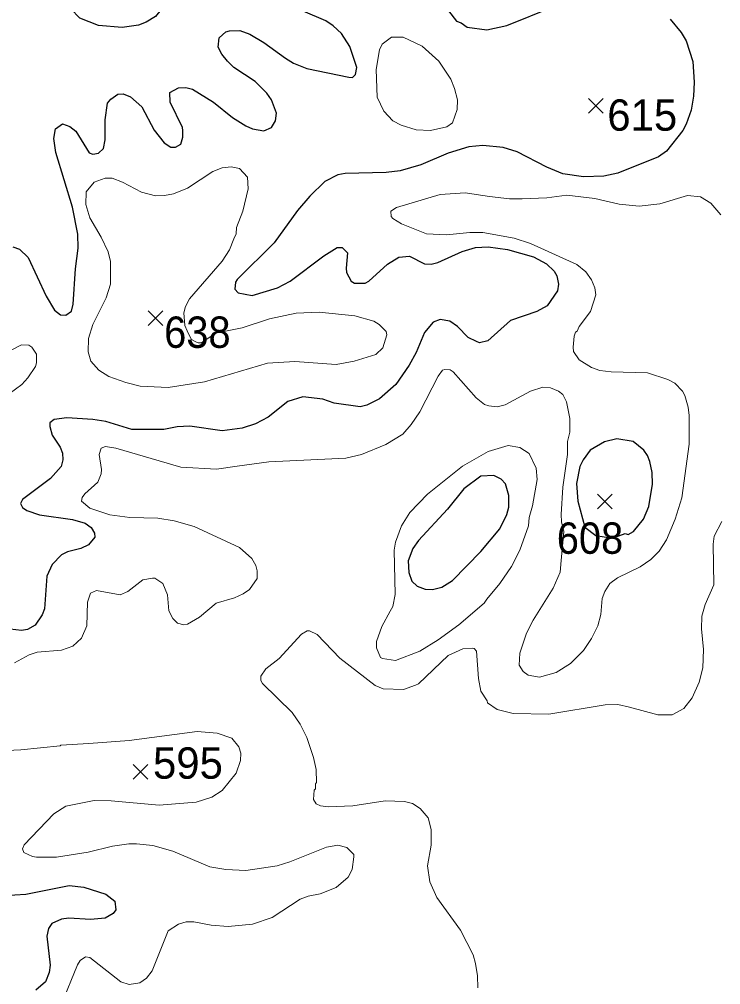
# Model space of a CAD drawing. Extents: x 423 to 448.8, y 7456.3 to 7484.
# Drawn here: x 434.858 to 436.648, y 7460.704 to 7463.168 of the extents above; entities that cross this region are included whole.
import ezdxf
from ezdxf.enums import TextEntityAlignment as Align

# ---------------------------------------------------------------- set-up
doc = ezdxf.new("R2010")
doc.units = 0
doc.header["$LTSCALE"] = 0.032
for name, color, linetype, lineweight in [('1', 7, 'Continuous', 25), ('2', 7, 'Continuous', 13), ('21', 7, 'Continuous', 25)]:
    doc.layers.add(name, color=color, linetype=linetype, lineweight=lineweight)
doc.layers.add('61', color=7, linetype='Continuous')

msp = doc.modelspace()

# ---------------------------------------------------------------- linework, layer by layer
at = {"layer": '1'}
for points in [[(434.9786, 7463.2394), (434.9778, 7463.2502), (434.9925, 7463.3028), (435.008, 7463.3236), (435.0475, 7463.3538), (435.0792, 7463.3616), (435.1062, 7463.3623), (435.148, 7463.3538), (435.1697, 7463.3415), (435.2083, 7463.3066), (435.2223, 7463.2811), (435.2315, 7463.2533), (435.2307, 7463.2146), (435.2199, 7463.193), (435.2052, 7463.1752), (435.182, 7463.1605), (435.1619, 7463.1527), (435.1202, 7463.1473), (435.0598, 7463.152), (435.0126, 7463.1705), (434.9894, 7463.1945)], [(436.4505, 7461.8919), (436.4644, 7461.9245), (436.4737, 7461.9817), (436.4729, 7462.0111), (436.4668, 7462.039), (436.4613, 7462.0544), (436.452, 7462.0683), (436.4242, 7462.09), (436.3825, 7462.097), (436.3515, 7462.0892), (436.3151, 7462.0683), (436.2966, 7462.0436), (436.2881, 7462.0266), (436.2803, 7461.9833), (436.2834, 7461.9384), (436.3009, 7461.872), (436.329, 7461.8501), (436.3715, 7461.8439), (436.4043, 7461.8556), (436.4118, 7461.8533), (436.4258, 7461.861)], [(436.0355, 7461.8092), (436.0839, 7461.8672), (436.1025, 7461.9044), (436.1071, 7461.9229), (436.1071, 7461.9523), (436.0986, 7461.9825), (436.0878, 7461.9941), (436.0692, 7462.0034), (436.0359, 7462.0018), (435.9926, 7461.9693), (435.9509, 7461.9175), (435.8766, 7461.8379), (435.8619, 7461.8169), (435.8503, 7461.786), (435.8518, 7461.7559), (435.8596, 7461.7342), (435.8735, 7461.721), (435.8936, 7461.7133), (435.9122, 7461.7125), (435.9361, 7461.7187), (435.9632, 7461.7357)]]:
    msp.add_lwpolyline(points, close=True, dxfattribs=at)
for points in [[(435.9532, 7463.1898), (435.9741, 7463.1628), (435.9856, 7463.1589), (436.0011, 7463.1481), (436.0514, 7463.1411), (436.1025, 7463.152), (436.22, 7463.1999)], [(434.9631, 7462.4133), (434.9763, 7462.4125), (434.991, 7462.4233), (434.9956, 7462.4412), (435.001, 7462.5309), (435.008, 7462.5835), (435.0072, 7462.6191), (434.9941, 7462.6887), (434.9508, 7462.8279), (434.9461, 7462.8635), (434.95, 7462.8882), (434.9686, 7462.9013), (434.9871, 7462.8944), (435.0026, 7462.882), (435.0366, 7462.8271), (435.0459, 7462.8232), (435.0598, 7462.8263), (435.073, 7462.8379), (435.0768, 7462.8604), (435.0768, 7462.9114), (435.083, 7462.9539), (435.0915, 7462.964), (435.1093, 7462.9764), (435.1233, 7462.9779), (435.1418, 7462.9702), (435.1704, 7462.9446), (435.2021, 7462.8851), (435.2277, 7462.8526), (435.2447, 7462.8418), (435.2563, 7462.8418), (435.2702, 7462.8488), (435.2756, 7462.8666), (435.2749, 7462.8836), (435.2741, 7462.8913), (435.2431, 7462.9563), (435.2423, 7462.981), (435.264, 7462.9926), (435.2826, 7462.9934), (435.2996, 7462.9895), (435.3538, 7462.9563), (435.4024, 7462.9176), (435.4357, 7462.8959), (435.4528, 7462.8882), (435.4821, 7462.8835), (435.5015, 7462.8921), (435.5115, 7462.9083), (435.5146, 7462.9284), (435.5015, 7462.9625), (435.4899, 7462.9795), (435.4597, 7463.0089), (435.4056, 7463.0452), (435.3893, 7463.0607), (435.3746, 7463.0785), (435.3653, 7463.0971), (435.3677, 7463.1203), (435.3854, 7463.1357), (435.394, 7463.138), (435.421, 7463.1396), (435.4466, 7463.1295), (435.4822, 7463.1086), (435.537, 7463.0684), (435.558, 7463.056), (435.592, 7463.0421), (435.6987, 7463.0205), (435.708, 7463.0197), (435.7157, 7463.0266), (435.7196, 7463.0445), (435.7018, 7463.0986), (435.6801, 7463.1318), (435.6592, 7463.1512), (435.6399, 7463.1636), (435.5827, 7463.1883)], [(436.5193, 7463.1682), (436.5472, 7463.1341), (436.5596, 7463.1125), (436.5766, 7463.0599), (436.5805, 7463.0073), (436.5789, 7462.9718), (436.5727, 7462.9362), (436.5596, 7462.9006), (436.5511, 7462.8836), (436.51, 7462.8317), (436.4891, 7462.817), (436.3856, 7462.7753), (436.35, 7462.7675), (436.2974, 7462.766), (436.2448, 7462.7737), (436.2046, 7462.7907), (436.1288, 7462.8294), (436.0932, 7462.841), (436.0406, 7462.8456), (436.005, 7462.8426), (435.9524, 7462.8263), (435.8828, 7462.7962), (435.8302, 7462.7807), (435.7946, 7462.7768), (435.6894, 7462.7745), (435.6709, 7462.7706), (435.6376, 7462.7536), (435.5997, 7462.7165), (435.568, 7462.6801), (435.5084, 7462.5974), (435.4141, 7462.5038), (435.4094, 7462.4968), (435.4079, 7462.479), (435.4164, 7462.4697), (435.452, 7462.4628), (435.5169, 7462.4829), (435.5494, 7462.4991), (435.6353, 7462.5641), (435.6693, 7462.5858), (435.6817, 7462.585), (435.6956, 7462.5718), (435.6917, 7462.5324), (435.6933, 7462.5216), (435.7049, 7462.4999), (435.7134, 7462.4945), (435.7404, 7462.4945), (435.7498, 7462.4991), (435.7977, 7462.5432), (435.8263, 7462.561), (435.8534, 7462.5634), (435.8921, 7462.544), (435.9091, 7462.5425), (435.9261, 7462.5471), (435.988, 7462.575), (436.022, 7462.585), (436.0545, 7462.5873), (436.104, 7462.5803), (436.1705, 7462.5618), (436.203, 7462.544)], [(434.8417, 7462.5873), (434.8587, 7462.5811), (434.8804, 7462.5602), (434.9268, 7462.4613), (434.9477, 7462.4257), (434.9631, 7462.4133)], [(436.203, 7462.544), (436.2231, 7462.5254), (436.2301, 7462.5131), (436.2339, 7462.4922), (436.2316, 7462.4752), (436.2053, 7462.4365), (436.1783, 7462.4218), (436.1117, 7462.3994), (436.0537, 7462.3468), (436.0321, 7462.3421), (436.0251, 7462.3452), (436.0035, 7462.356), (435.9764, 7462.3839), (435.9563, 7462.3978), (435.9323, 7462.4017), (435.9145, 7462.3947), (435.8921, 7462.3685), (435.8704, 7462.3174), (435.8526, 7462.2849), (435.8186, 7462.2362), (435.7776, 7462.199), (435.7451, 7462.1828), (435.7281, 7462.1789), (435.6616, 7462.1882), (435.6322, 7462.1983), (435.5812, 7462.2045), (435.5432, 7462.1928), (435.4929, 7462.1526), (435.4605, 7462.1356), (435.4265, 7462.124), (435.3754, 7462.1178), (435.2934, 7462.1294), (435.2609, 7462.1279), (435.2269, 7462.1209), (435.1449, 7462.1209), (435.0784, 7462.141), (435.0459, 7462.1465), (434.9794, 7462.1511), (434.9469, 7462.1464), (434.936, 7462.138), (434.936, 7462.1287), (434.9422, 7462.1062), (434.9624, 7462.0761), (434.9686, 7462.0606), (434.9693, 7462.0436), (434.9647, 7462.0266), (434.9376, 7461.9956), (434.8657, 7461.9423), (434.861, 7461.9322), (434.8657, 7461.9221), (434.8773, 7461.9144), (434.9098, 7461.9028), (434.9933, 7461.8912), (435.0258, 7461.8819), (435.0412, 7461.8711), (435.0498, 7461.8564), (435.0505, 7461.8463), (435.0343, 7461.8262), (435.015, 7461.8169), (434.9809, 7461.8085), (434.9655, 7461.8007), (434.9415, 7461.7767), (434.9283, 7461.7466), (434.9221, 7461.6631), (434.9167, 7461.6476), (434.8982, 7461.6213), (434.8789, 7461.6104), (434.8634, 7461.6081), (434.82, 7461.6128)], [(434.8185, 7460.9314), (434.8742, 7460.9352), (434.9856, 7460.9568), (435.0227, 7460.953), (435.0784, 7460.9352), (435.1016, 7460.9174), (435.1047, 7460.895), (435.0977, 7460.8857), (435.0769, 7460.8741), (435.0397, 7460.8702), (434.984, 7460.8741), (434.9655, 7460.871), (434.9407, 7460.8602), (434.9322, 7460.8478), (434.9283, 7460.8277), (434.9368, 7460.7535), (434.9338, 7460.7349), (434.9245, 7460.7109), (434.9005, 7460.69)]]:
    msp.add_lwpolyline(points, dxfattribs=at)
at = {"layer": '2'}
for points in [[(435.9686, 7462.9911), (435.9593, 7463.0151), (435.9284, 7463.0607), (435.8859, 7463.0993), (435.8379, 7463.1218), (435.8271, 7463.1225), (435.8078, 7463.1218), (435.7838, 7463.104), (435.7776, 7463.0901), (435.7683, 7463.0398), (435.7714, 7462.9687), (435.7884, 7462.9331), (435.8116, 7462.9091), (435.8325, 7462.8975), (435.8704, 7462.8859), (435.9076, 7462.8843), (435.9493, 7462.8936), (435.9632, 7462.9037), (435.9756, 7462.9377), (435.9764, 7462.9625)], [(435.4055, 7462.6074), (435.411, 7462.6206), (435.4125, 7462.6368), (435.428, 7462.6778), (435.4419, 7462.7351), (435.4404, 7462.7652), (435.4195, 7462.7869), (435.3986, 7462.7915), (435.3754, 7462.7884), (435.3522, 7462.7791), (435.2872, 7462.7366), (435.2517, 7462.7227), (435.2285, 7462.718), (435.2053, 7462.7172), (435.1697, 7462.7265), (435.1217, 7462.7521), (435.0946, 7462.7621), (435.0768, 7462.7621), (435.049, 7462.752), (435.0289, 7462.7273), (435.0274, 7462.6949), (435.0381, 7462.6608), (435.0668, 7462.6121), (435.0846, 7462.5742), (435.0908, 7462.5494), (435.0908, 7462.4922), (435.0799, 7462.4566), (435.0459, 7462.3886), (435.0343, 7462.353), (435.0335, 7462.319), (435.0405, 7462.2957), (435.0613, 7462.2725), (435.0861, 7462.2563), (435.1295, 7462.2408), (435.1666, 7462.2315), (435.2377, 7462.2284), (435.3306, 7462.2423), (435.4914, 7462.2903), (435.561, 7462.2942), (435.6662, 7462.2872), (435.7126, 7462.2957), (435.7675, 7462.312), (435.7861, 7462.329), (435.7961, 7462.3623), (435.7938, 7462.3707), (435.776, 7462.3893), (435.7629, 7462.3978), (435.7142, 7462.411), (435.6229, 7462.4202), (435.5641, 7462.4179), (435.4961, 7462.4032), (435.4265, 7462.3808), (435.3583, 7462.3665), (435.323, 7462.3417), (435.3146, 7462.3424), (435.3083, 7462.3443), (435.2975, 7462.3506), (435.2907, 7462.3635), (435.2863, 7462.3729), (435.28, 7462.3862), (435.2782, 7462.4189), (435.2823, 7462.4345), (435.2922, 7462.4543), (435.3754, 7462.5502), (435.394, 7462.5796)], [(435.8046, 7461.6569), (435.8108, 7461.6692), (435.817, 7461.7002), (435.8147, 7461.8131), (435.8178, 7461.8332), (435.8333, 7461.875), (435.8542, 7461.909), (435.8998, 7461.9562), (435.9887, 7462.0273), (436.0545, 7462.0652), (436.1056, 7462.0799), (436.135, 7462.0753), (436.1589, 7462.0598), (436.1767, 7462.0219), (436.1798, 7461.9933), (436.1674, 7461.926), (436.1589, 7461.8966), (436.1573, 7461.875), (436.1349, 7461.8131), (436.114, 7461.7713), (436.0846, 7461.728), (436.0514, 7461.6878), (436.0444, 7461.6777), (435.9795, 7461.622), (435.9269, 7461.5842), (435.8805, 7461.5555), (435.8178, 7461.5315), (435.7845, 7461.5362), (435.7799, 7461.5393), (435.7699, 7461.5641), (435.7699, 7461.5795), (435.783, 7461.6182)]]:
    msp.add_lwpolyline(points, close=True, dxfattribs=at)
for points in [[(435.8109, 7462.6592), (435.807, 7462.6647), (435.8062, 7462.6778), (435.8209, 7462.6879), (435.9323, 7462.7211), (435.9957, 7462.725), (436.0576, 7462.7157), (436.1087, 7462.7095), (436.1411, 7462.7095), (436.2046, 7462.7126), (436.2556, 7462.7188), (436.3268, 7462.7103), (436.3886, 7462.6956), (436.4397, 7462.691), (436.4923, 7462.6971), (436.5634, 7462.718), (436.5967, 7462.7149), (436.623, 7462.6987), (436.6485, 7462.6686)], [(435.018, 7461.9477), (435.025, 7461.9569), (435.0583, 7461.9864), (435.0668, 7462.008), (435.0676, 7462.0188), (435.0614, 7462.0575), (435.0668, 7462.073), (435.0776, 7462.0776), (435.1047, 7462.0737), (435.2702, 7462.025), (435.3615, 7462.0196), (435.4141, 7462.0273), (435.4945, 7462.0382), (435.691, 7462.0474), (435.7312, 7462.0575), (435.7931, 7462.083), (435.8363, 7462.1093), (435.858, 7462.1333), (435.8805, 7462.1658), (435.9269, 7462.2571), (435.9377, 7462.2725), (435.9439, 7462.2741), (435.9578, 7462.2733), (435.9648, 7462.2679), (436.0243, 7462.2021), (436.0452, 7462.1851), (436.0561, 7462.1812), (436.0777, 7462.1789), (436.0978, 7462.1836), (436.1628, 7462.2184), (436.1937, 7462.2292), (436.2138, 7462.2269), (436.234, 7462.2184), (436.2448, 7462.2106), (436.2548, 7462.1913), (436.2633, 7462.1488), (436.2633, 7462.114), (436.2572, 7462.09), (436.2572, 7462.0575), (436.2447, 7461.974), (436.2409, 7461.9044), (436.2417, 7461.885), (436.2477, 7461.861), (436.2412, 7461.7868), (436.2385, 7461.7566), (436.22, 7461.7157), (436.1697, 7461.6344), (436.1527, 7461.6012), (436.1349, 7461.5501), (436.1334, 7461.5199), (436.1442, 7461.5029), (436.1566, 7461.4936), (436.1852, 7461.489), (436.2278, 7461.5006), (436.2649, 7461.5238), (436.2974, 7461.5571), (436.3182, 7461.5873), (436.3345, 7461.6197), (436.3422, 7461.6491), (436.3453, 7461.6894), (436.3523, 7461.7079), (436.3654, 7461.728), (436.3848, 7461.7427), (436.4428, 7461.7705), (436.4698, 7461.7891), (436.4907, 7461.81), (436.51, 7461.8394), (436.5317, 7461.892), (436.5487, 7461.9469), (436.5673, 7462.0838), (436.5673, 7462.1565), (436.565, 7462.1782), (436.5565, 7462.2076), (436.5503, 7462.2184), (436.5309, 7462.2393), (436.5132, 7462.2485), (436.4614, 7462.2655), (436.3685, 7462.2679), (436.3391, 7462.2717), (436.3182, 7462.2795), (436.2865, 7462.2988), (436.2726, 7462.3197), (436.2711, 7462.3313), (436.2741, 7462.3592), (436.2772, 7462.3692), (436.2819, 7462.3715), (436.2865, 7462.3839), (436.3159, 7462.4218), (436.3291, 7462.4644), (436.3267, 7462.4829), (436.3182, 7462.503), (436.3036, 7462.5231), (436.2804, 7462.5417), (436.1628, 7462.5958), (436.121, 7462.609), (436.0406, 7462.6237), (436.0081, 7462.6237), (435.9478, 7462.6175), (435.8967, 7462.6206), (435.8333, 7462.6461), (435.8109, 7462.6592)], [(434.8317, 7462.2122), (434.8641, 7462.2354), (434.8796, 7462.2524), (434.899, 7462.2818), (434.902, 7462.2911), (434.902, 7462.3128), (434.8896, 7462.3313), (434.8819, 7462.336), (434.8633, 7462.3367), (434.8386, 7462.3243)], [(434.8456, 7461.5254), (434.8827, 7461.5455), (434.9036, 7461.5524), (434.9655, 7461.5579), (434.9948, 7461.5679), (435.0165, 7461.5888), (435.0304, 7461.6197), (435.032, 7461.6801), (435.0397, 7461.7033), (435.0552, 7461.7102), (435.1155, 7461.6994), (435.1348, 7461.7071), (435.1735, 7461.7373), (435.1975, 7461.7419), (435.2037, 7461.7419), (435.2246, 7461.728), (435.2362, 7461.6986), (435.2393, 7461.6584), (435.2501, 7461.6383), (435.2617, 7461.6267), (435.278, 7461.6228), (435.2872, 7461.6244), (435.3182, 7461.6421), (435.3607, 7461.6777), (435.4071, 7461.6916), (435.4296, 7461.7017), (435.445, 7461.7126), (435.4651, 7461.7404), (435.4651, 7461.7605), (435.4613, 7461.7736), (435.4512, 7461.7915), (435.4202, 7461.82), (435.3043, 7461.8734), (435.2532, 7461.8881), (435.2114, 7461.8943), (435.1403, 7461.8966), (435.0892, 7461.9028), (435.0382, 7461.9198), (435.0165, 7461.9384), (435.018, 7461.9477)], [(436.6508, 7461.8858), (436.6315, 7461.8486), (436.6284, 7461.8286), (436.6307, 7461.7249), (436.6083, 7461.6739), (436.5998, 7461.6445), (436.599, 7461.612), (436.6037, 7461.5594), (436.6021, 7461.513), (436.5928, 7461.4759), (436.575, 7461.4357), (436.5542, 7461.4086), (436.524, 7461.3931), (436.4876, 7461.3931), (436.4149, 7461.4124), (436.3856, 7461.4194), (436.3531, 7461.4186), (436.2092, 7461.3946), (436.1179, 7461.3962), (436.0777, 7461.4062), (436.0529, 7461.4233), (436.0522, 7461.4287), (436.0359, 7461.4527), (436.0298, 7461.4852), (436.0251, 7461.5548), (436.0189, 7461.5617), (436.0143, 7461.5625), (435.9895, 7461.561), (435.9524, 7461.5439), (435.8766, 7461.472), (435.8689, 7461.4681), (435.8387, 7461.4573), (435.7869, 7461.4589), (435.766, 7461.4673), (435.6763, 7461.5377), (435.6183, 7461.598), (435.5982, 7461.6073), (435.5927, 7461.6073), (435.578, 7461.5988), (435.5208, 7461.5362), (435.4875, 7461.5099), (435.4744, 7461.4913), (435.4744, 7461.4805), (435.4783, 7461.4728), (435.5541, 7461.3985), (435.575, 7461.3691), (435.592, 7461.3351), (435.609, 7461.2841), (435.6159, 7461.2531), (435.6167, 7461.2198), (435.6136, 7461.2167), (435.6136, 7461.2036), (435.6105, 7461.2005), (435.609, 7461.1765), (435.6159, 7461.1657), (435.6268, 7461.1603), (435.6461, 7461.158), (435.7095, 7461.1603), (435.7915, 7461.1734), (435.841, 7461.1719), (435.8611, 7461.1665), (435.8812, 7461.1533), (435.9013, 7461.1301), (435.9091, 7461.1), (435.9091, 7461.0598), (435.8998, 7461.0072), (435.906, 7460.9669), (435.9238, 7460.9267), (435.9841, 7460.8432), (436.0158, 7460.7798), (436.022, 7460.7581), (436.0274, 7460.7264), (436.0282, 7460.6962)], [(434.9771, 7461.1595), (435.049, 7461.1742), (435.0923, 7461.1734), (435.2145, 7461.1626), (435.3089, 7461.1696), (435.3491, 7461.1827), (435.3754, 7461.1997), (435.4117, 7461.2438), (435.4226, 7461.2763), (435.4234, 7461.2949), (435.4179, 7461.3111), (435.4002, 7461.3328), (435.363, 7461.3459), (435.312, 7461.3498), (435.1387, 7461.3274), (435.0351, 7461.3196), (434.9639, 7461.3157), (434.9624, 7461.3134), (434.8618, 7461.3034), (434.7907, 7461.3003)], [(434.9647, 7460.6529), (435.0064, 7460.755), (435.0134, 7460.7658), (435.0266, 7460.7751), (435.0382, 7460.7736), (435.1171, 7460.7117), (435.1387, 7460.7047), (435.1658, 7460.7086), (435.1828, 7460.721), (435.1967, 7460.7395), (435.2377, 7460.8416), (435.264, 7460.8587), (435.2841, 7460.864), (435.3035, 7460.864), (435.3476, 7460.8556), (435.3909, 7460.8524), (435.4528, 7460.8587), (435.503, 7460.8757), (435.575, 7460.9221), (435.5951, 7460.9298), (435.626, 7460.936), (435.6662, 7460.9522), (435.6971, 7460.9785), (435.7072, 7460.9979), (435.7118, 7461.0304), (435.7118, 7461.0366), (435.694, 7461.0543), (435.6709, 7461.0598), (435.6415, 7461.0551), (435.5487, 7461.0172), (435.5162, 7461.0072), (435.4357, 7460.9955), (435.3847, 7460.9979), (435.3445, 7461.0048), (435.2501, 7461.045), (435.1991, 7461.059), (435.1573, 7461.0636), (435.1372, 7461.0636), (435.0954, 7461.0574), (435.0335, 7461.0419), (434.9531, 7461.0296), (434.9021, 7461.0296), (434.8912, 7461.0311), (434.8695, 7461.0412), (434.8665, 7461.0505), (434.8703, 7461.0613), (434.9461, 7461.1402), (434.9771, 7461.1595)]]:
    msp.add_lwpolyline(points, dxfattribs=at)
at = {"layer": '21'}
for p, q in [((436.3102, 7462.9659), (436.3477, 7462.9284)), ((436.3477, 7462.9659), (436.3102, 7462.9284)), ((435.1869, 7462.4236), (435.2244, 7462.3861)), ((435.2244, 7462.4236), (435.1869, 7462.3861)), ((436.3332, 7461.9562), (436.3707, 7461.9187)), ((436.3707, 7461.9562), (436.3332, 7461.9187)), ((435.1482, 7461.2658), (435.1857, 7461.2283)), ((435.1857, 7461.2658), (435.1482, 7461.2283))]:
    msp.add_line(p, q, dxfattribs=at)

# ---------------------------------------------------------------- texts
at = {"layer": '61'}
for s, p in [('615', (436.4477, 7462.8835)), ('595', (435.2883, 7461.2297))]:
    msp.add_text(s, height=0.08, dxfattribs=at).set_placement(p, align=Align.CENTER)
at = {"layer": '61', "width": 0.95}
for s, p in [('638', (435.3124, 7462.3293)), ('608', (436.3144, 7461.8037))]:
    msp.add_text(s, height=0.08, dxfattribs=at).set_placement(p, align=Align.CENTER)

doc.saveas('drawing.dxf')
